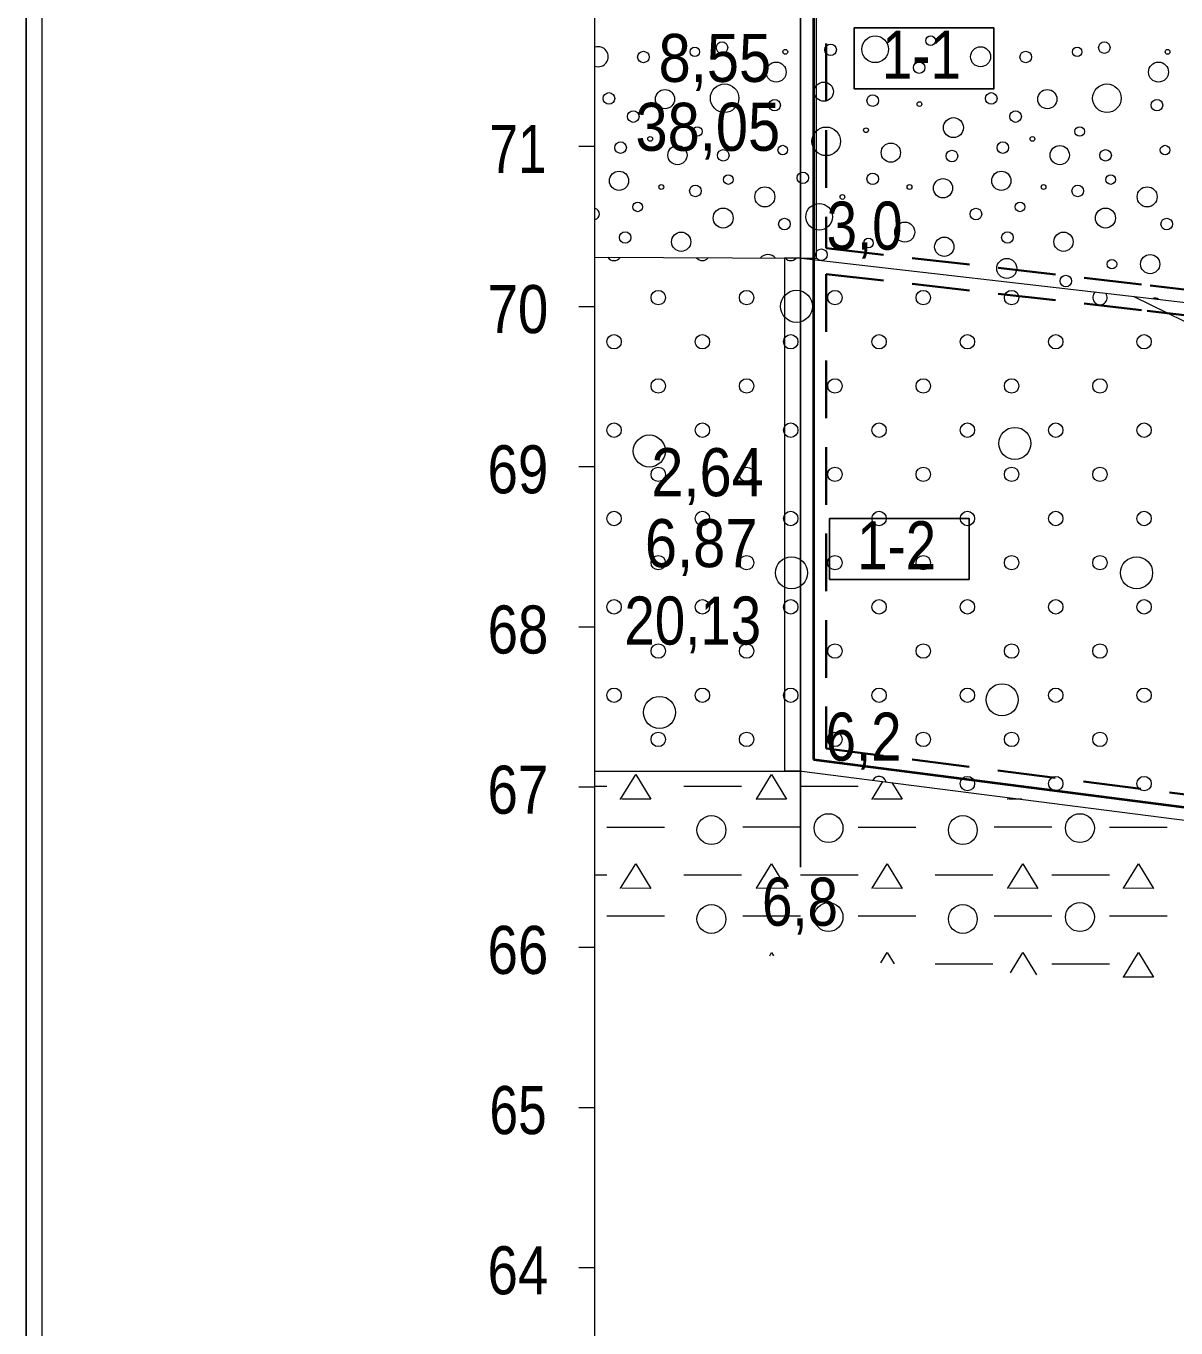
# Model space of a CAD drawing. Extents: x 640104 to 640970, y 6442278 to 6442689.
# Drawn here: x 640103.6 to 640175.4, y 6442357 to 6442438.2 of the extents above; entities that cross this region are included whole.
import ezdxf
from ezdxf.enums import TextEntityAlignment as Align

# ---------------------------------------------------------------- set-up
doc = ezdxf.new("R2010")
doc.units = 0
doc.header["$LTSCALE"] = 1.2
doc.linetypes.add('MEDIUM_DASHED', pattern=[4.5, 3, -1.5])
for name, color, linetype, lineweight in [('30', 7, 'Continuous', 13), ('31', 7, 'Continuous', 13), ('32', 7, 'Continuous', 25), ('33', 7, 'Continuous', 13), ('35', 7, 'Continuous', 35), ('41', 7, 'Continuous', 13), ('42', 7, 'Continuous', 13), ('46', 7, 'Continuous', 13), ('47', 7, 'Continuous', 13), ('50', 7, 'Continuous', 13)]:
    doc.layers.add(name, color=color, linetype=linetype, lineweight=lineweight)

msp = doc.modelspace()

# ---------------------------------------------------------------- linework, layer by layer
at = {"layer": '30'}
for p, q in [((640139.08, 6442300.75), (640139.08, 6442460.75)), ((640138.08, 6442430.75), (640139.08, 6442430.75)), ((640138.08, 6442420.75), (640139.08, 6442420.75)), ((640138.08, 6442410.75), (640139.08, 6442410.75)), ((640138.08, 6442400.75), (640139.08, 6442400.75)), ((640138.08, 6442390.75), (640139.08, 6442390.75)), ((640138.08, 6442380.75), (640139.08, 6442380.75)), ((640138.08, 6442370.75), (640139.08, 6442370.75)), ((640138.08, 6442360.75), (640139.08, 6442360.75))]:
    msp.add_line(p, q, dxfattribs=at)
at = {"layer": '31'}
for points in [[(640139.08, 6442423.82), (640151.96, 6442423.75), (640173.66, 6442421.26), (640213.16, 6442416.61), (640233.94, 6442414.53), (640242.79, 6442413.66), (640295.17, 6442389.83), (640328.15, 6442387.74), (640358.78, 6442385.66), (640377.96, 6442384.87), (640391.41, 6442383.72), (640397.31, 6442383.01), (640414.42, 6442381.45)], [(640172.72, 6442421.37), (640177.91, 6442418.83), (640183.79, 6442415.68), (640190.09, 6442411.98), (640198.03, 6442407.87), (640204.05, 6442404.86), (640210.76, 6442401.17), (640217.06, 6442397.2), (640224.59, 6442391.99), (640228.68, 6442389.35), (640232.99, 6442386.57), (640236.43, 6442384.42), (640240.06, 6442382.68), (640242.81, 6442381.6)], [(640139.08, 6442391.74), (640152, 6442391.74), (640184.83, 6442387.53), (640224.44, 6442383.27), (640230.93, 6442382.67), (640242.81, 6442381.6), (640246.59, 6442379.93), (640268.17, 6442370.27), (640295.32, 6442359.75), (640299.34, 6442358.9), (640322.09, 6442356.12), (640340.84, 6442354.22), (640374.54, 6442350.71), (640388.93, 6442348.78), (640409.14, 6442347), (640414.32, 6442346.47), (640439.11, 6442345.27), (640478.03, 6442341.77)]]:
    msp.add_lwpolyline(points, dxfattribs=at)
at = {"layer": '32'}
msp.add_line((640151.92, 6442453.75), (640151.92, 6442385.75), dxfattribs=at)
at = {"layer": '33'}
for points in [[(640152.92, 6442423.75), (640152.92, 6442449.62), (640151.92, 6442449.72), (640151.92, 6442423.75), (640151.96, 6442423.75)], [(640150.92, 6442423.75), (640150.92, 6442391.75), (640151.92, 6442391.75), (640151.92, 6442423.75), (640151.92, 6442423.75), (640151.24, 6442423.75)]]:
    msp.add_lwpolyline(points, close=True, dxfattribs=at)
at = {"layer": '33', "lineweight": 25}
for points in [[(640155.27, 6442438.13), (640163.98, 6442438.13), (640163.98, 6442434.33), (640155.27, 6442434.33)], [(640153.73, 6442407.51), (640162.44, 6442407.51), (640162.44, 6442403.71), (640153.73, 6442403.71)]]:
    msp.add_lwpolyline(points, close=True, dxfattribs=at)
at = {"layer": '35', "lineweight": 40}
msp.add_line((640152.72, 6442448.83), (640152.72, 6442392.46), dxfattribs=at)
at = {"layer": '35', "linetype": 'MEDIUM_DASHED'}
for p, q in [((640153.52, 6442447.95), (640153.52, 6442424.38)), ((640153.52, 6442422.77), (640153.52, 6442393.16))]:
    msp.add_line(p, q, dxfattribs=at)
for points in [[(640153.52, 6442424.38), (640173.75, 6442422.06), (640213.24, 6442417.41), (640234.02, 6442415.33), (640243, 6442414.44), (640295.36, 6442390.62), (640328.2, 6442388.54), (640358.82, 6442386.46), (640378.01, 6442385.67), (640391.49, 6442384.52), (640397.4, 6442383.81), (640411.83, 6442382.49)], [(640153.52, 6442422.77), (640173.56, 6442420.47), (640213.07, 6442415.82), (640233.86, 6442413.74), (640242.58, 6442412.88), (640294.97, 6442389.04), (640328.09, 6442386.94), (640358.73, 6442384.86), (640377.91, 6442384.07), (640391.32, 6442382.92), (640397.23, 6442382.22), (640405.71, 6442381.44)], [(640153.52, 6442393.16), (640185.01, 6442389.12), (640224.6, 6442384.86), (640231.07, 6442384.26), (640243.22, 6442383.17), (640247.24, 6442381.39), (640268.78, 6442371.75), (640295.64, 6442361.35)]]:
    msp.add_lwpolyline(points, dxfattribs=at)
at = {"layer": '35', "lineweight": 40}
msp.add_lwpolyline([(640152.72, 6442392.46), (640184.92, 6442388.33), (640224.52, 6442384.07), (640231, 6442383.47), (640243.02, 6442382.39), (640246.92, 6442380.66), (640268.47, 6442371.01), (640295.48, 6442360.55)], dxfattribs=at)
at = {"layer": '41'}
for centre, radius in [((640147.012, 6442436.904), 0.36), ((640153.792, 6442436.761), 0.36), ((640156.575, 6442436.8), 0.834), ((640160.033, 6442437.338), 0.3), ((640170.881, 6442436.904), 0.36), ((640142.105, 6442436.317), 0.36), ((640145.314, 6442436.639), 0.3), ((640150.961, 6442436.639), 0.15), ((640163.155, 6442436.332), 0.624), ((640165.974, 6442436.317), 0.36), ((640169.183, 6442436.639), 0.3), ((640174.83, 6442436.639), 0.15), ((640150.392, 6442435.375), 0.624), ((640159.32, 6442435.652), 0.36), ((640174.261, 6442435.375), 0.624), ((640147.172, 6442433.743), 0.889), ((640153.364, 6442434.155), 0.6), ((640171.041, 6442433.743), 0.889), ((640139.952, 6442433.731), 0.36), ((640143.454, 6442433.687), 0.6), ((640156.421, 6442433.594), 0.36), ((640163.821, 6442433.731), 0.36), ((640167.323, 6442433.687), 0.6), ((640141.471, 6442432.599), 0.36), ((640150.297, 6442433.307), 0.36), ((640159.337, 6442433.378), 0.15), ((640165.34, 6442432.599), 0.36), ((640174.166, 6442433.307), 0.36), ((640161.459, 6442431.907), 0.624), ((640142.524, 6442431.203), 0.15), ((640145.47, 6442431.668), 0.3), ((640153.515, 6442431.053), 0.893), ((640156.001, 6442431.746), 0.15), ((640166.393, 6442431.203), 0.15), ((640169.339, 6442431.668), 0.3), ((640140.679, 6442430.662), 0.36), ((640144.228, 6442430.192), 0.6), ((640147.09, 6442430.178), 0.36), ((640150.805, 6442430.504), 0.3), ((640157.552, 6442430.348), 0.6), ((640161.366, 6442430.136), 0.36), ((640164.548, 6442430.662), 0.36), ((640168.097, 6442430.192), 0.6), ((640170.959, 6442430.178), 0.36), ((640174.674, 6442430.504), 0.3), ((640140.583, 6442428.592), 0.6), ((640147.408, 6442428.667), 0.3), ((640152.06, 6442428.772), 0.36), ((640156.421, 6442428.715), 0.36), ((640164.452, 6442428.592), 0.6), ((640171.277, 6442428.667), 0.3), ((640143.22, 6442428.202), 0.15), ((640145.349, 6442427.955), 0.36), ((640149.684, 6442427.586), 0.624), ((640158.716, 6442428.202), 0.15), ((640160.81, 6442428.124), 0.6), ((640167.089, 6442428.202), 0.15), ((640169.218, 6442427.955), 0.36), ((640173.553, 6442427.586), 0.624), ((640141.747, 6442426.96), 0.3), ((640154.528, 6442427.581), 0.15), ((640165.616, 6442426.96), 0.3), ((640147.082, 6442426.266), 0.624), ((640153.076, 6442426.343), 0.835), ((640162.867, 6442426.514), 0.36), ((640170.951, 6442426.266), 0.624), ((640150.908, 6442425.89), 0.36), ((640158.422, 6442425.388), 0.624), ((640174.777, 6442425.89), 0.36), ((640140.962, 6442425.052), 0.36), ((640144.462, 6442424.785), 0.6), ((640156.157, 6442424.704), 0.3), ((640160.888, 6442424.473), 0.6), ((640164.831, 6442425.052), 0.36), ((640168.331, 6442424.785), 0.6), ((640153.215, 6442423.976), 0.36), ((640173.741, 6442423.39), 0.6), ((640164.79, 6442423.119), 0.624), ((640171.355, 6442423.387), 0.3), ((640168.481, 6442422.331), 0.36)]:
    msp.add_circle(centre, radius, dxfattribs=at)
for centre, radius, start, end in [((640139.286, 6442436.332), 0.624, 250.85588, 109.14412), ((640138.998, 6442426.514), 0.36, 283.33012, 76.66988), ((640149.872, 6442423.39), 0.6, 37.93156, 141.47161), ((640174.053, 6442420.975), 0.3, 45.76008, 120.81183)]:
    msp.add_arc(centre, radius, start, end, dxfattribs=at)
at = {"layer": '42'}
for centre in [(640143.03, 6442421.297), (640148.546, 6442421.297), (640154.061, 6442421.297), (640159.577, 6442421.297), (640165.092, 6442421.297), (640140.272, 6442418.54), (640145.788, 6442418.54), (640151.303, 6442418.54), (640156.819, 6442418.54), (640162.334, 6442418.54), (640167.85, 6442418.54), (640173.365, 6442418.54), (640143.03, 6442415.782), (640148.546, 6442415.782), (640154.061, 6442415.782), (640159.577, 6442415.782), (640165.092, 6442415.782), (640170.607, 6442415.782), (640140.272, 6442413.024), (640145.788, 6442413.024), (640151.303, 6442413.024), (640156.819, 6442413.024), (640162.334, 6442413.024), (640167.85, 6442413.024), (640173.365, 6442413.024), (640143.03, 6442410.266), (640148.546, 6442410.266), (640154.061, 6442410.266), (640159.577, 6442410.266), (640165.092, 6442410.266), (640170.607, 6442410.266), (640140.272, 6442407.509), (640145.788, 6442407.509), (640151.303, 6442407.509), (640156.819, 6442407.509), (640162.334, 6442407.509), (640167.85, 6442407.509), (640173.365, 6442407.509), (640143.03, 6442404.751), (640148.546, 6442404.751), (640154.061, 6442404.751), (640159.577, 6442404.751), (640165.092, 6442404.751), (640170.607, 6442404.751), (640140.272, 6442401.993), (640145.788, 6442401.993), (640151.303, 6442401.993), (640156.819, 6442401.993), (640162.334, 6442401.993), (640167.85, 6442401.993), (640173.365, 6442401.993), (640143.03, 6442399.235), (640148.546, 6442399.235), (640154.061, 6442399.235), (640159.577, 6442399.235), (640165.092, 6442399.235), (640170.607, 6442399.235), (640140.272, 6442396.478), (640145.788, 6442396.478), (640151.303, 6442396.478), (640156.819, 6442396.478), (640162.334, 6442396.478), (640167.85, 6442396.478), (640173.365, 6442396.478), (640143.03, 6442393.72), (640148.546, 6442393.72), (640154.061, 6442393.72), (640159.577, 6442393.72), (640165.092, 6442393.72), (640170.607, 6442393.72), (640162.334, 6442390.962), (640167.85, 6442390.962), (640173.365, 6442390.962)]:
    msp.add_circle(centre, 0.45, dxfattribs=at)
for centre, start, end in [((640140.272, 6442424.055), 212.55613, 326.84705), ((640145.788, 6442424.055), 217.02715, 322.37603), ((640151.303, 6442424.055), 221.78242, 317.62075), ((640170.607, 6442421.297), 129.6841, 37.22509), ((640156.819, 6442390.962), 13.77435, 151.59744)]:
    msp.add_arc(centre, 0.45, start, end, dxfattribs=at)
at = {"layer": '46'}
for p, q in [((640139.82, 6442390.79), (640139.08, 6442390.79)), ((640148.22, 6442390.79), (640144.62, 6442390.79)), ((640155.52, 6442390.79), (640151.92, 6442390.79)), ((640165.74, 6442389.98), (640164.93, 6442389.98)), ((640143.42, 6442388.23), (640139.82, 6442388.23)), ((640151.92, 6442388.24), (640148.32, 6442388.24)), ((640159.11, 6442388.23), (640155.51, 6442388.23)), ((640167.61, 6442388.24), (640164.01, 6442388.24)), ((640174.81, 6442388.23), (640171.21, 6442388.23)), ((640139.82, 6442385.24), (640139.08, 6442385.24)), ((640148.22, 6442385.24), (640144.62, 6442385.24)), ((640155.52, 6442385.24), (640151.92, 6442385.24)), ((640163.91, 6442385.24), (640160.31, 6442385.24)), ((640171.21, 6442385.24), (640167.61, 6442385.24)), ((640143.42, 6442382.68), (640139.82, 6442382.68)), ((640151.92, 6442382.68), (640148.32, 6442382.68)), ((640159.11, 6442382.68), (640155.51, 6442382.68)), ((640167.61, 6442382.68), (640164.01, 6442382.68)), ((640174.81, 6442382.68), (640171.21, 6442382.68)), ((640163.91, 6442379.68), (640160.31, 6442379.68)), ((640171.21, 6442379.68), (640167.61, 6442379.68))]:
    msp.add_line(p, q, dxfattribs=at)
for points in [[(640140.68, 6442389.96), (640140.68, 6442389.99), (640141.63, 6442391.52), (640142.56, 6442389.98), (640140.76, 6442389.99)], [(640149.15, 6442389.96), (640149.16, 6442389.99), (640150.1, 6442391.52), (640151.03, 6442389.98), (640149.23, 6442389.98)], [(640156.38, 6442389.96), (640156.38, 6442389.99), (640157.06, 6442391.09)], [(640157.62, 6442391.02), (640158.26, 6442389.98), (640156.46, 6442389.99)], [(640164.85, 6442389.96), (640164.85, 6442389.99), (640164.91, 6442390.09)], [(640140.68, 6442384.41), (640140.68, 6442384.43), (640141.63, 6442385.96), (640142.56, 6442384.42), (640140.76, 6442384.43)], [(640149.15, 6442384.41), (640149.16, 6442384.43), (640150.1, 6442385.96), (640151.03, 6442384.42), (640149.23, 6442384.43)], [(640156.38, 6442384.41), (640156.38, 6442384.43), (640157.33, 6442385.96), (640158.26, 6442384.42), (640156.46, 6442384.43)], [(640164.85, 6442384.41), (640164.85, 6442384.43), (640165.8, 6442385.96), (640166.73, 6442384.42), (640164.93, 6442384.43)], [(640172.07, 6442384.41), (640172.07, 6442384.43), (640173.02, 6442385.96), (640173.95, 6442384.42), (640172.15, 6442384.43)], [(640149.99, 6442380.22), (640150.1, 6442380.41), (640150.23, 6442380.2)], [(640156.93, 6442379.77), (640157.33, 6442380.41), (640157.75, 6442379.71)], [(640165.02, 6442379.14), (640165.8, 6442380.41), (640166.64, 6442379.02)], [(640172.07, 6442378.85), (640172.07, 6442378.88), (640173.02, 6442380.41), (640173.95, 6442378.87), (640172.15, 6442378.88)]]:
    msp.add_lwpolyline(points, dxfattribs=at)
for centre in [(640153.663, 6442388.184), (640169.358, 6442388.184), (640146.35, 6442388.061), (640162.045, 6442388.061), (640146.35, 6442382.507), (640153.663, 6442382.629), (640162.045, 6442382.507), (640169.358, 6442382.629)]:
    msp.add_circle(centre, 0.9, dxfattribs=at)
at = {"layer": '47'}
for centre in [(640151.665, 6442420.753), (640142.475, 6442411.722), (640165.29, 6442412.198), (640151.348, 6442404.118), (640172.895, 6442404.118), (640164.498, 6442396.196), (640143.109, 6442395.404)]:
    msp.add_circle(centre, 1, dxfattribs=at)
at = {"layer": '50', "lineweight": 25}
msp.add_lwpolyline([(640103.56, 6442688.99), (640970.3, 6442688.99), (640970.3, 6442282.54), (640103.56, 6442282.54)], close=True, dxfattribs=at)
at = {"layer": '50'}
msp.add_lwpolyline([(640104.56, 6442687.99), (640969.3, 6442687.99), (640969.3, 6442283.54), (640104.56, 6442283.54)], close=True, dxfattribs=at)

# ---------------------------------------------------------------- texts
at = {"layer": '30'}
for s, width, p in [('71', 0.8, (640134.275, 6442429.08)), ('70', 0.85, (640134.27, 6442419.08)), ('69', 0.85, (640134.27, 6442409.08)), ('68', 0.85, (640134.275, 6442399.08)), ('67', 0.85, (640134.27, 6442389.08)), ('66', 0.85, (640134.27, 6442379.08)), ('65', 0.8, (640134.28, 6442369.08)), ('64', 0.85, (640134.27, 6442359.08))]:
    msp.add_text(s, height=3, dxfattribs=dict(at, width=width)).set_placement(p, align=Align.CENTER)
at = {"layer": '32', "width": 0.85}
for s, p in [('3,0', (640155.915, 6442424.29)), ('6,2', (640155.85, 6442392.39)), ('6,8', (640151.88, 6442382.09))]:
    msp.add_text(s, height=3, dxfattribs=at).set_placement(p, align=Align.CENTER)
at = {"layer": '33'}
for s, width, p in [('8,55', 0.9, (640146.565, 6442434.76)), ('1-1', 0.85, (640159.46, 6442434.96)), ('38,05', 0.9, (640146.125, 6442430.46)), ('2,64', 0.9, (640146.11, 6442408.9)), ('6,87', 0.9, (640145.71, 6442404.47)), ('1-2', 0.85, (640157.915, 6442404.34)), ('20,13', 0.85, (640145.185, 6442399.64))]:
    msp.add_text(s, height=3, dxfattribs=dict(at, width=width)).set_placement(p, align=Align.CENTER)

doc.saveas('drawing.dxf')
